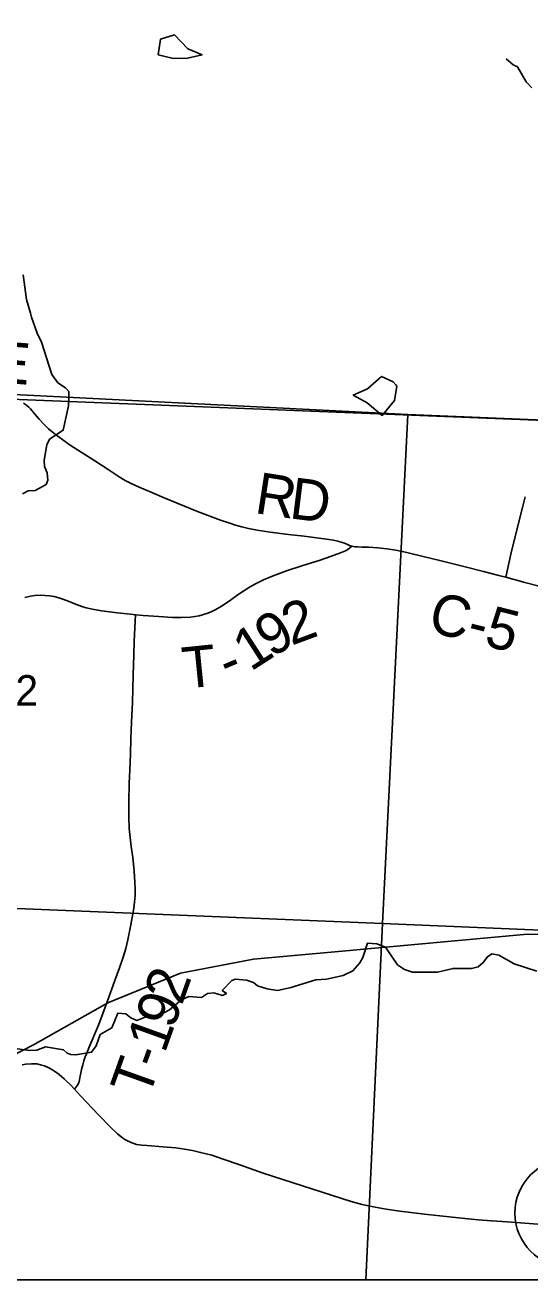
# Model space of a CAD drawing. Extents: x 0 to 34, y 0 to 22.
# Drawn here: x 4.217 to 4.911, y 14.1 to 15.827 of the extents above; entities that cross this region are included whole.
import ezdxf

# ---------------------------------------------------------------- set-up
doc = ezdxf.new("R2010")
doc.units = 0
for name, color, linetype in [('GM_X_County_Road', 7, 'Continuous'), ('GM_X_County_Road_Text', 7, 'Continuous'), ('GM_X_Minor_Lake', 7, 'Continuous'), ('GM_X_Minor_River', 7, 'Continuous'), ('GM_X_Rail_Line', 7, 'Continuous'), ('GM_X_Section', 7, 'Continuous'), ('GM_X_Section_Text', 7, 'Continuous'), ('GM_X_State_Route', 7, 'Continuous'), ('GM_X_Township_Road', 7, 'Continuous'), ('GM_X_Township_Road_Text', 7, 'Continuous'), ('GM_X_Unincorporated', 7, 'Continuous'), ('GM_X_Unincorporated_Text', 7, 'Continuous'), ('SH_Data', 7, 'Continuous')]:
    doc.layers.add(name, color=color, linetype=linetype)

msp = doc.modelspace()

# ---------------------------------------------------------------- linework, layer by layer
at = {"layer": 'GM_X_County_Road'}
for points in [[(4.2144, 15.3064), (4.2171, 15.3048), (4.2196, 15.3029), (4.2219, 15.3008), (4.2241, 15.2986), (4.2301, 15.2914), (4.236, 15.2843), (4.2423, 15.2775), (4.249, 15.2712), (4.2585, 15.2633), (4.2684, 15.2558), (4.2786, 15.2487), (4.3127, 15.2271), (4.3308, 15.2151), (4.3463, 15.2049), (4.3543, 15.2001), (4.3625, 15.1959), (4.3738, 15.1908), (4.391, 15.1837), (4.4081, 15.1764), (4.4539, 15.1575), (4.4856, 15.1455), (4.4968, 15.1416), (4.506, 15.1387), (4.515, 15.1361), (4.5239, 15.134), (4.5362, 15.1316), (4.5541, 15.129), (4.5792, 15.1259), (4.6008, 15.1234), (4.6316, 15.1195), (4.6408, 15.118), (4.6469, 15.1166), (4.6529, 15.1147), (4.656, 15.1137), (4.6601, 15.1119), (4.663, 15.1108), (4.6661, 15.1099)], [(4.6661, 15.1099), (4.6705, 15.1089), (4.6743, 15.1086), (4.6801, 15.1083), (4.6895, 15.1081), (4.7019, 15.1073), (4.7143, 15.1059), (4.7266, 15.104), (4.7418, 15.1009), (4.766, 15.0951), (4.7871, 15.0898), (4.8202, 15.0815), (4.8473, 15.0747), (4.8684, 15.0693), (4.878, 15.0668)], [(4.878, 15.0668), (4.9044, 15.0599), (4.9435, 15.0498), (4.9706, 15.0431), (5.0099, 15.0338), (5.0734, 15.019), (5.0828, 15.017), (5.0888, 15.0157)]]:
    msp.add_lwpolyline(points, dxfattribs=at)
at = {"layer": 'GM_X_Minor_Lake'}
for points in [[(4.4603, 15.7856), (4.4406, 15.7943), (4.4221, 15.8133), (4.4028, 15.8072), (4.3998, 15.786)], [(4.3998, 15.786), (4.421, 15.781), (4.4402, 15.7814), (4.4603, 15.7856), (4.4406, 15.7943), (4.4221, 15.8133), (4.4028, 15.8072), (4.3998, 15.786)], [(4.3998, 15.786), (4.421, 15.781), (4.4402, 15.7814), (4.4603, 15.7856)], [(4.7267, 15.3317), (4.7232, 15.336), (4.707, 15.3431), (4.6877, 15.326), (4.6681, 15.3177)], [(4.7267, 15.3317), (4.7232, 15.336), (4.707, 15.3431), (4.6877, 15.326), (4.6681, 15.3177), (4.6874, 15.307), (4.7082, 15.2896), (4.7248, 15.3101), (4.7282, 15.3298), (4.7267, 15.3317)], [(4.6681, 15.3177), (4.6874, 15.307), (4.7082, 15.2896), (4.7248, 15.3101), (4.7282, 15.3298), (4.7267, 15.3317)]]:
    msp.add_lwpolyline(points, dxfattribs=at)
at = {"layer": 'GM_X_Minor_River'}
for points in [[(4.9139, 15.7404), (4.9063, 15.7487), (4.8941, 15.7692), (4.888, 15.7722), (4.8785, 15.7805)], [(4.2471, 15.2105), (4.2436, 15.2192), (4.2428, 15.2279), (4.2465, 15.2492), (4.2502, 15.2568), (4.2691, 15.2691), (4.2765, 15.3026), (4.2771, 15.3162), (4.2767, 15.3223), (4.2722, 15.3276), (4.2619, 15.3344), (4.2535, 15.3461), (4.2393, 15.3904), (4.2332, 15.4026), (4.2255, 15.4249), (4.224, 15.4302), (4.2186, 15.4492), (4.2139, 15.483)], [(4.2132, 15.1815), (4.2211, 15.1857), (4.2305, 15.1865), (4.2456, 15.1945), (4.2482, 15.2006), (4.2471, 15.2105)], [(4.8587, 14.5486), (4.8527, 14.5447), (4.8471, 14.5367), (4.8399, 14.5306), (4.8308, 14.5283), (4.8055, 14.5285), (4.7839, 14.5235), (4.7768, 14.5235), (4.7696, 14.5234), (4.7495, 14.5233), (4.7389, 14.527), (4.729, 14.5334), (4.7127, 14.558), (4.7005, 14.5625), (4.6877, 14.5632), (4.6813, 14.5438), (4.6772, 14.5362), (4.6678, 14.5251), (4.6542, 14.519), (4.6312, 14.5139), (4.6168, 14.5127), (4.5885, 14.5042), (4.5828, 14.5023), (4.5639, 14.4984), (4.5499, 14.5006), (4.5366, 14.5047), (4.5309, 14.5092), (4.5215, 14.5126), (4.5063, 14.5136), (4.501, 14.5121), (4.4879, 14.4983), (4.4936, 14.4942), (4.4883, 14.4915), (4.4762, 14.4949), (4.4675, 14.4941), (4.4596, 14.4887), (4.4421, 14.4901), (4.432, 14.4855), (4.4154, 14.4714), (4.4014, 14.4641), (4.3818, 14.4613), (4.3704, 14.4571), (4.3621, 14.4608), (4.3553, 14.4661), (4.3443, 14.4672), (4.3361, 14.447), (4.3202, 14.4378), (4.3143, 14.4222), (4.3082, 14.4135), (4.2867, 14.4099), (4.2795, 14.4103), (4.2746, 14.4118), (4.2696, 14.4167), (4.2447, 14.4207), (4.233, 14.4161), (4.2227, 14.4157), (4.1962, 14.4193)], [(4.9209, 14.5246), (4.8898, 14.5347), (4.8686, 14.5467), (4.8587, 14.5486)]]:
    msp.add_lwpolyline(points, dxfattribs=at)
at = {"layer": 'GM_X_Rail_Line'}
for points in [[(2.1, 18.4819), (2.1, 15.4153), (3.9123, 15.3323), (3.9451, 15.3313), (3.973, 15.329), (4.0133, 15.3262), (4.0257, 15.3251), (4.0381, 15.324), (4.0782, 15.3206), (4.1061, 15.3185), (4.1743, 15.3141), (4.1849, 15.3132), (4.1956, 15.3121), (4.1973, 15.3118), (5.1044, 15.2759), (5.2458, 15.271), (5.4522, 15.2638), (5.479, 15.731), (5.4821, 15.8189)], [(4.1532, 14.3849), (4.2282, 14.4236), (4.3306, 14.4812), (4.4305, 14.5219), (4.5308, 14.5414), (4.648, 14.5518), (4.9079, 14.5757), (5.1792, 14.5733), (5.2237, 14.5733), (5.272, 14.5707), (5.3144, 14.561), (5.3776, 14.525), (5.5225, 14.4206), (5.5518, 14.4183), (5.6045, 14.4272), (5.6536, 14.4306), (5.6957, 14.4175), (5.7467, 14.3883), (6.0004, 14.1469), (6.0402, 14.1)]]:
    msp.add_lwpolyline(points, dxfattribs=at)
msp.add_lwpolyline([(2.1, 15.4153), (2.1, 14.1), (6.4223, 14.1), (6.4607, 14.8895), (6.4764, 15.22), (6.2705, 15.2288), (5.4522, 15.2638), (5.2458, 15.271), (5.1044, 15.2759), (4.1973, 15.3118), (4.1956, 15.3121), (4.1849, 15.3132), (4.1743, 15.3141), (4.1061, 15.3185), (4.0782, 15.3206), (4.0381, 15.324), (4.0257, 15.3251), (4.0133, 15.3262), (3.973, 15.329), (3.9451, 15.3313), (3.9123, 15.3323)], close=True, dxfattribs=at)
at = {"layer": 'GM_X_Section'}
for points in [[(3.7314, 15.3424), (4.7434, 15.2908), (4.7084, 14.5904), (3.7021, 14.6318)], [(5.4613, 15.2612), (5.438, 14.5597), (4.7084, 14.5904), (4.7434, 15.2908)]]:
    msp.add_lwpolyline(points, close=True, dxfattribs=at)
at = {"layer": 'GM_X_State_Route'}
for points in [[(4.2127, 14.3957), (4.2179, 14.3968), (4.2257, 14.3973), (4.2327, 14.3971), (4.2381, 14.396), (4.2432, 14.3944), (4.2502, 14.3914), (4.2572, 14.3874), (4.2637, 14.3827), (4.271, 14.3763), (4.28, 14.3675), (4.2846, 14.3625), (4.293, 14.3533), (4.3183, 14.3266), (4.334, 14.3103), (4.3438, 14.3008), (4.3491, 14.2969), (4.354, 14.2933), (4.3566, 14.2916), (4.3625, 14.2889), (4.3702, 14.2865), (4.3772, 14.2856), (4.3847, 14.2848), (4.4061, 14.2832), (4.4239, 14.2818), (4.436, 14.28), (4.447, 14.2779), (4.4582, 14.2754), (4.4735, 14.2714), (4.4894, 14.266), (4.5121, 14.2582)], [(4.5121, 14.2582), (4.5443, 14.247), (4.6653, 14.2077), (4.6803, 14.2039), (4.6985, 14.2), (4.7137, 14.1973), (4.7321, 14.1947), (4.766, 14.1903), (4.8, 14.1866), (4.8216, 14.1844), (4.8401, 14.1828), (4.8585, 14.1813), (4.8801, 14.1799), (5.0254, 14.1687)]]:
    msp.add_lwpolyline(points, dxfattribs=at)
at = {"layer": 'GM_X_Township_Road'}
for points in [[(4.878, 15.0668), (4.8852, 15.0985), (4.8968, 15.1469), (4.9013, 15.1649), (4.9047, 15.1775)], [(4.3685, 15.0152), (4.3791, 15.0144), (4.4008, 15.0127), (4.4194, 15.0117), (4.4317, 15.0116), (4.4441, 15.0121), (4.4502, 15.0127), (4.4562, 15.0139), (4.4621, 15.0155), (4.4679, 15.0174), (4.4736, 15.0197), (4.4791, 15.0225), (4.487, 15.0272), (4.4974, 15.034), (4.51, 15.043), (4.5176, 15.0484), (4.5255, 15.0534), (4.5337, 15.058), (4.5449, 15.0634), (4.5535, 15.067), (4.5619, 15.0704), (4.5765, 15.0757), (4.5974, 15.0827), (4.6226, 15.0906), (4.6369, 15.0955), (4.6505, 15.1004), (4.6576, 15.1034), (4.6609, 15.1053), (4.6661, 15.1099)], [(4.2162, 15.0392), (4.2242, 15.0409), (4.2299, 15.0416), (4.2373, 15.0421), (4.2437, 15.042), (4.2501, 15.0415), (4.2567, 15.0402), (4.263, 15.0386), (4.2686, 15.0367), (4.2774, 15.0335), (4.286, 15.03), (4.2947, 15.0268), (4.3006, 15.0249), (4.3096, 15.0228), (4.3218, 15.0206), (4.3433, 15.0178), (4.3619, 15.0159), (4.3685, 15.0152)], [(4.2846, 14.3625), (4.2872, 14.3661), (4.2892, 14.3688), (4.2907, 14.3713), (4.2916, 14.3751), (4.2927, 14.3806), (4.2934, 14.3844), (4.2945, 14.3897), (4.296, 14.3957), (4.2974, 14.4015), (4.2994, 14.4068), (4.302, 14.4131), (4.3043, 14.4192), (4.3175, 14.4507), (4.3296, 14.4827), (4.3402, 14.5119), (4.3464, 14.5294), (4.3516, 14.544), (4.3552, 14.5561), (4.3579, 14.5678), (4.3623, 14.5888), (4.3641, 14.5989), (4.3664, 14.6117), (4.3674, 14.6196), (4.3681, 14.6288), (4.3683, 14.638), (4.3679, 14.6472), (4.3668, 14.6626), (4.365, 14.6811), (4.3628, 14.6964), (4.3612, 14.7087), (4.3601, 14.7211), (4.3594, 14.7366), (4.3593, 14.7583), (4.36, 14.7832), (4.3608, 14.8018), (4.3616, 14.8235), (4.3624, 14.8452), (4.3632, 14.8669), (4.3643, 14.8949), (4.3651, 14.9135), (4.3656, 14.9321), (4.3663, 14.9601), (4.3669, 14.9787), (4.3681, 15.0064), (4.3685, 15.0152)]]:
    msp.add_lwpolyline(points, dxfattribs=at)
at = {"layer": 'GM_X_Unincorporated'}
msp.add_circle((4.9649, 14.1919), 0.0744, dxfattribs=at)
at = {"layer": 'GM_X_Unincorporated_Text'}
for points in [[(3.681, 14.1), (4.6857, 14.1), (4.7084, 14.5904), (3.7021, 14.6318)], [(4.6857, 14.1), (5.4179, 14.1), (5.4247, 14.2527), (5.438, 14.5597), (4.7084, 14.5904)]]:
    msp.add_lwpolyline(points, close=True, dxfattribs=at)
at = {"layer": 'SH_Data'}
msp.add_line((2.1, 14.1), (8.9, 14.1), dxfattribs=at)

# ---------------------------------------------------------------- texts
at = {"layer": 'GM_X_County_Road_Text'}
for s, height, rotation, p in [('GROVE', 0.05682, 355.4646, (3.9478, 15.3534)), ('R', 0.0568, 351.1915, (4.5311, 15.1556)), ('D', 0.0568, 352.8674, (4.579, 15.1482)), ('C-5', 0.05682, 345.7497, (4.7689, 14.993))]:
    msp.add_text(s, height=height, rotation=rotation, dxfattribs=at).set_placement(p)
at = {"layer": 'GM_X_Section_Text'}
msp.add_text('2', height=0.0419, rotation=0, dxfattribs=at).set_placement((4.2034, 14.8903))
at = {"layer": 'GM_X_Township_Road_Text'}
for s, rotation, p in [('2', 20.3575, (4.583, 14.9725)), ('9', 32.0026, (4.5561, 14.9553)), ('1', 32.8221, (4.5268, 14.9364)), ('T', 5.7694, (4.4357, 14.9135)), ('-', 22.8997, (4.4959, 14.9223)), ('2', 70.5109, (4.4323, 14.4767)), ('9', 70.3288, (4.4205, 14.4435)), ('1', 70.2767, (4.4087, 14.4105)), ('T', 70.2626, (4.3864, 14.3485)), ('-', 70.2516, (4.4008, 14.3885))]:
    msp.add_text(s, height=0.0568, rotation=rotation, dxfattribs=at).set_placement(p)

doc.saveas('drawing.dxf')
